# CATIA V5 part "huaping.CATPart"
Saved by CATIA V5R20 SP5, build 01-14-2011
Part number: 花瓶
Material "Wallpaper Strip 2": density 2120 kg/m3, Young's modulus 2.56e+10 Pa, Poisson ratio 0.22
Bounding box of the stored display mesh (mm): x -34.886 to 34.886, y -34.886 to 34.85, z 0 to 100
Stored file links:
  E:\180211226\huaping.CATPart
  C:\Program Files\Dassault Systemes\B20\intel_a\startup\materials\Catalog.CATMaterial
  C:\Program Files\Dassault Systemes\B20\intel_a\startup\materials\alcantara.jpg
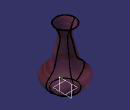
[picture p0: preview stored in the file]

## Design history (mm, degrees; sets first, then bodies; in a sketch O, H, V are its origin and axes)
Body1 (main body), material "Wallpaper Strip 2"
  Plane1: type Offset, RefPlane xy-plane, Offset 20
  Plane2: type Offset, RefPlane Plane1, Offset 20
  Plane3: type Offset, RefPlane Plane2, Offset 20
  Plane4: type Offset, RefPlane Plane3, Offset 20
  Plane5: type Offset, RefPlane Plane4, Offset 20
  Sketch1 on Plane5, origin (0, 0, 100), H (1, 0, 0), V (0, 1, 0)
    circle A1 centre (0, 0) radius 17.5
    radius A1 = 17.5
  Sketch2 on Plane4, origin (0, 0, 80), H (1, 0, 0), V (0, 1, 0)
    circle A1 centre (0, 0) radius 10
    radius A1 = 10
  Sketch3 on Plane3, origin (0, 0, 60), H (1, 0, 0), V (0, 1, 0)
    circle A1 centre (0, 0) radius 15
    radius A1 = 15
  Sketch4 on Plane2, origin (0, 0, 40), H (1, 0, 0), V (0, 1, 0)
    circle A1 centre (0, 0) radius 20
    radius A1 = 20
  Sketch5 on Plane1, origin (0, 0, 20), H (1, 0, 0), V (0, 1, 0)
    circle A1 centre (0, 0) radius 35
    radius A1 = 35
  Sketch6 on xy-plane, origin (0, 0, 0), H (1, 0, 0), V (0, 1, 0)
    circle A1 centre (0, 0) radius 20
    radius A1 = 20
  Loft1: solid, Sections (Sketch1; Sketch2; Sketch3; Sketch4; Sketch5; Sketch6)
  Shell1: ExtOffset 0, Face face of Loft1, IntOffset 1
